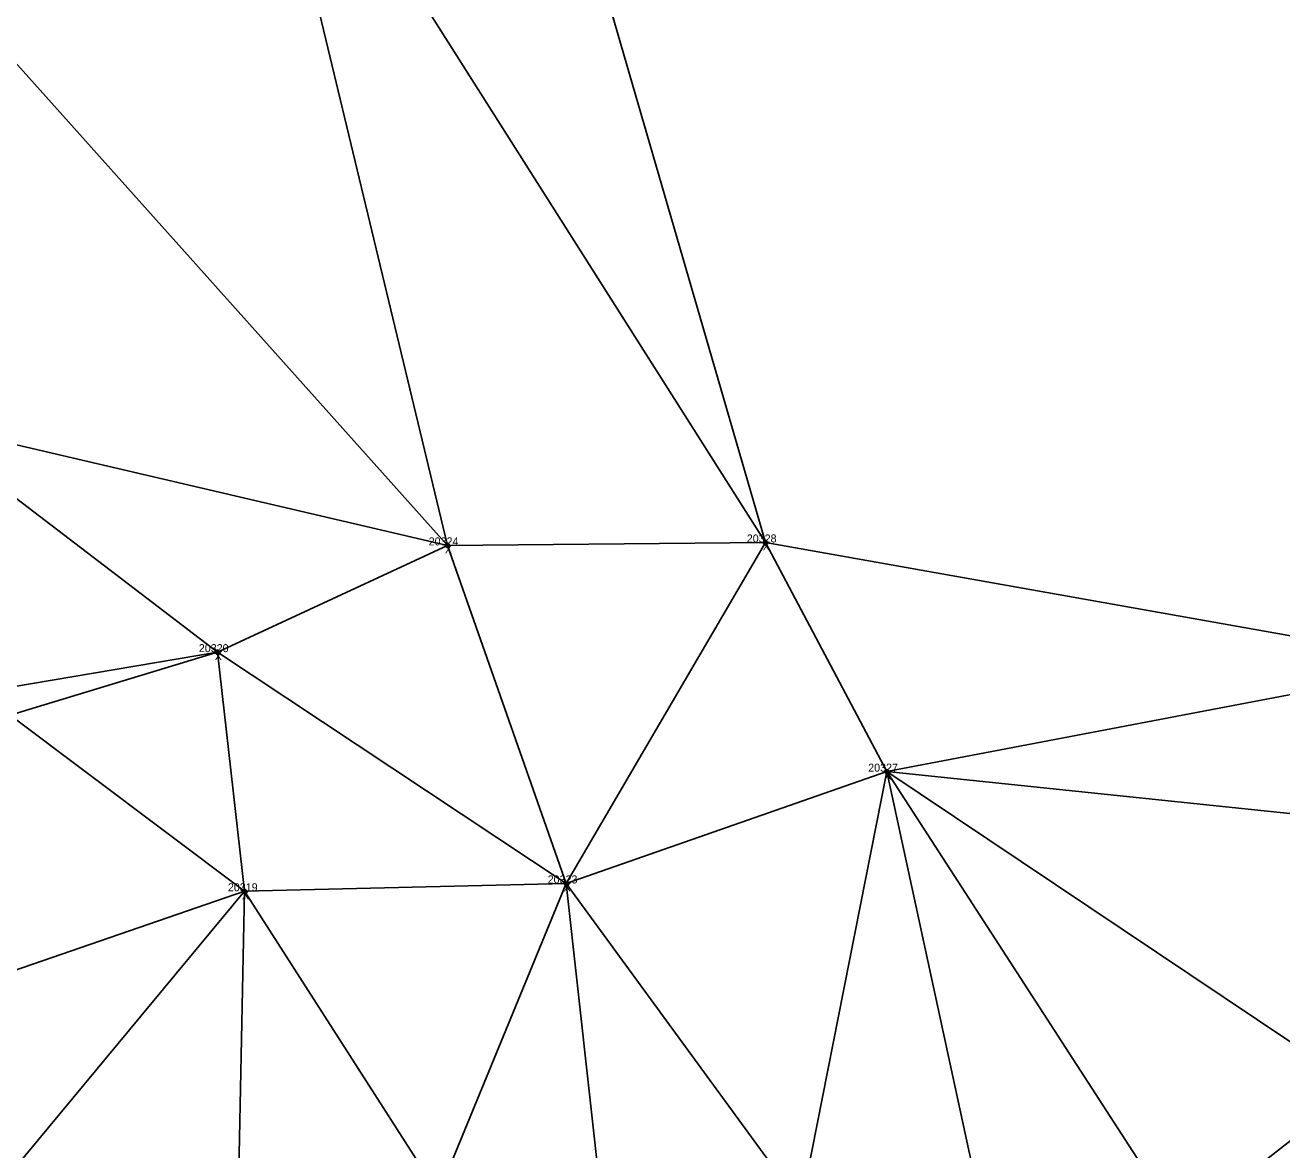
# Model space of a CAD drawing. Extents: x 1966740 to 1969291, y 1117379 to 1118460.
# Drawn here: x 1967940 to 1968097.1, y 1117960.2 to 1118100.7 of the extents above; entities that cross this region are included whole.
import ezdxf

# ---------------------------------------------------------------- set-up
doc = ezdxf.new("R2010")
doc.units = 0
for name, color, linetype in [('Level 30', 7, 'Continuous'), ('Level 35', 7, 'Continuous'), ('Level 52', 7, 'Continuous'), ('Level 62', 7, 'Continuous')]:
    doc.layers.add(name, color=color, linetype=linetype)

msp = doc.modelspace()

# ---------------------------------------------------------------- linework, layer by layer
at = {"layer": 'Level 30'}
for centre in [(1967992.8, 1118035.73), (1968032.52, 1118036.1), (1967964.05, 1118022.39), (1968047.69, 1118007.46), (1968007.64, 1117993.49), (1967967.44, 1117992.51)]:
    msp.add_circle(centre, 0.25, dxfattribs=at)
at = {"layer": 'Level 35'}
for points in [[(1967968.41, 1118137.26), (1967990.37, 1118181.32), (1968032.52, 1118036.1)], [(1967929.51, 1118106.48), (1967968.41, 1118137.26), (1967992.8, 1118035.73)], [(1967968.41, 1118137.26), (1968032.52, 1118036.1), (1967992.8, 1118035.73)], [(1967926.25, 1118051.25), (1967929.51, 1118106.48), (1967992.8, 1118035.73)], [(1967926.25, 1118051.25), (1967992.8, 1118035.73), (1967964.05, 1118022.39)], [(1967926.25, 1118051.25), (1967964.05, 1118022.39), (1967938.24, 1118018.03)], [(1967964.05, 1118022.39), (1967992.8, 1118035.73), (1968007.64, 1117993.49)], [(1967992.8, 1118035.73), (1968032.52, 1118036.1), (1968007.64, 1117993.49)], [(1968007.64, 1117993.49), (1968032.52, 1118036.1), (1968047.69, 1118007.46)], [(1968032.52, 1118036.1), (1968118.08, 1118020.88), (1968047.69, 1118007.46)], [(1967938.17, 1118014.53), (1967938.24, 1118018.03), (1967964.05, 1118022.39)], [(1967938.17, 1118014.53), (1967964.05, 1118022.39), (1967967.44, 1117992.51)], [(1967964.05, 1118022.39), (1968007.64, 1117993.49), (1967967.44, 1117992.51)], [(1968047.69, 1118007.46), (1968118.08, 1118020.88), (1968111.65, 1118000.8)], [(1967924.02, 1117977.55), (1967938.17, 1118014.53), (1967967.44, 1117992.51)], [(1968007.64, 1117993.49), (1968047.69, 1118007.46), (1968037, 1117953.28)], [(1968037, 1117953.28), (1968047.69, 1118007.46), (1968059.56, 1117952.62)], [(1968047.69, 1118007.46), (1968111.65, 1118000.8), (1968106.63, 1117967.98)], [(1968047.69, 1118007.46), (1968106.63, 1117967.98), (1968084.49, 1117950.65)], [(1968047.69, 1118007.46), (1968084.49, 1117950.65), (1968059.56, 1117952.62)], [(1967967.44, 1117992.51), (1968007.64, 1117993.49), (1967991.67, 1117954.7)], [(1967991.67, 1117954.7), (1968007.64, 1117993.49), (1968012.01, 1117954.01)], [(1968007.64, 1117993.49), (1968037, 1117953.28), (1968012.01, 1117954.01)], [(1967924.02, 1117977.55), (1967967.44, 1117992.51), (1967937.28, 1117956.15)], [(1967937.28, 1117956.15), (1967967.44, 1117992.51), (1967966.69, 1117955.54)], [(1967966.69, 1117955.54), (1967967.44, 1117992.51), (1967991.67, 1117954.7)], [(1968084.49, 1117950.65), (1968106.63, 1117967.98), (1968105.42, 1117949)]]:
    msp.add_lwpolyline(points, close=True, dxfattribs=at)

# ---------------------------------------------------------------- texts
at = {"layer": 'Level 52'}
for s, p in [('20328', (1968030.2, 1118036.1)), ('20324', (1967990.45, 1118035.73)), ('20320', (1967961.73, 1118022.39)), ('20327', (1968045.37, 1118007.46)), ('20319', (1967965.36, 1117992.51)), ('20323', (1968005.32, 1117993.49))]:
    msp.add_text(s, height=1, dxfattribs=at).set_placement(p)
at = {"layer": 'Level 62'}
for p in [(1967992.46, 1118034.73), (1968032.18, 1118035.1), (1967963.71, 1118021.39), (1968047.36, 1118006.46), (1968007.3, 1117992.49), (1967967.11, 1117991.51)]:
    msp.add_text('X', height=1, dxfattribs=at).set_placement(p)

doc.saveas('drawing.dxf')
